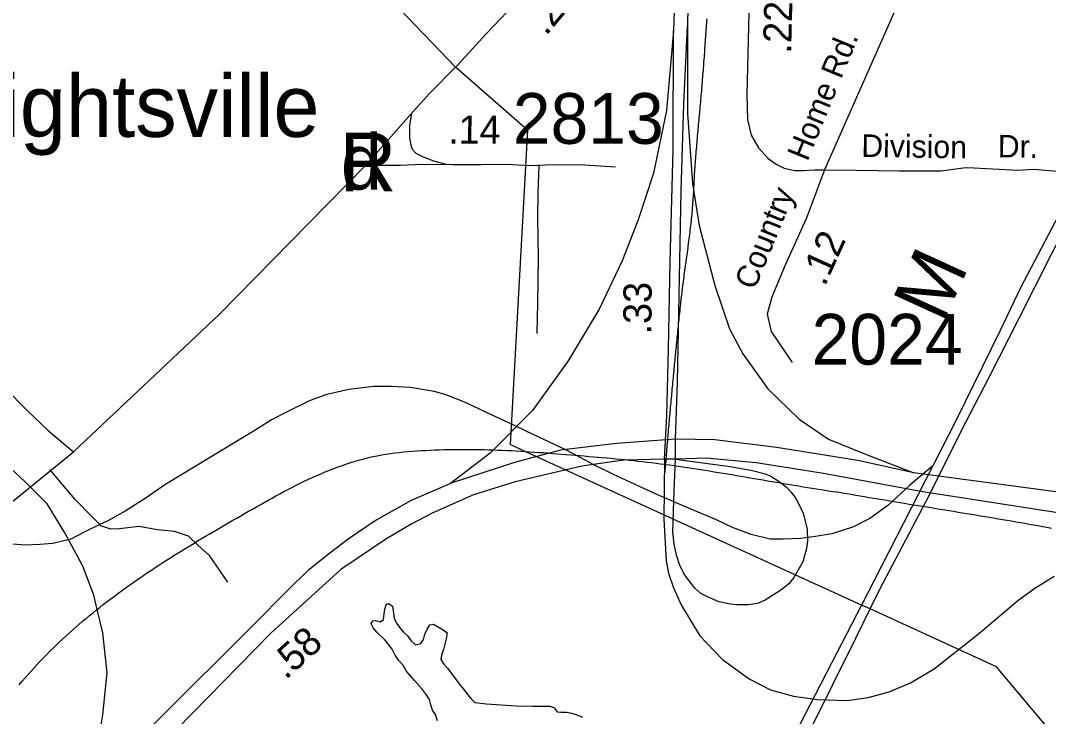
# Model space of a CAD drawing. Extents: x 1945482 to 2853149, y 66427 to 1015778.
# Drawn here: x 2321253 to 2324243, y 186898 to 188923 of the extents above; entities that cross this region are included whole.
import ezdxf

# ---------------------------------------------------------------- set-up
doc = ezdxf.new("R2010")
doc.units = 0
for name, color, linetype in [('Old_Level_11', 7, 'Continuous'), ('Old_Level_17', 7, 'Continuous'), ('Old_Level_22', 7, 'Continuous'), ('Old_Level_28', 7, 'Continuous'), ('Old_Level_29', 7, 'Continuous'), ('Old_Level_3', 7, 'Continuous'), ('Old_Level_32', 7, 'Continuous'), ('Old_Level_35', 7, 'Continuous'), ('Old_Level_44', 7, 'Continuous'), ('Old_Level_47', 7, 'Continuous'), ('Old_Level_56', 7, 'Continuous'), ('Old_Level_60', 7, 'Continuous'), ('Old_Level_8', 7, 'Continuous'), ('Old_Level_9', 7, 'Continuous')]:
    doc.layers.add(name, color=color, linetype=linetype)

msp = doc.modelspace()

# ---------------------------------------------------------------- linework, layer by layer
at = {"layer": 'Old_Level_28'}
for points in [[(2324358.8, 187539.7), (2323851.7, 187607.2), (2323688.9, 187643.3), (2323451.6, 187680.9), (2323272.1, 187703.2), (2323157.8, 187705.3), (2322986.2, 187693), (2322823.1, 187673), (2322689.2, 187637.3), (2322508.7, 187577.8), (2322388.6, 187526.7), (2322287.2, 187469.7), (2322206.2, 187414.6), (2322152.2, 187373.5), (2322090.6, 187323.8), (2322050.6, 187285.9), (2321910.1, 187144.3), (2321439.2, 186676.5), (2321001.4, 186215.9)], [(2323157.6, 187647), (2323126.2, 187647), (2323007.9, 187643.8), (2322885.3, 187626.5), (2322691.9, 187581.1), (2322570.8, 187543.2), (2322449.8, 187490.3), (2322389.3, 187457.8), (2322315.8, 187414.6), (2322184, 187325.9), (2321980.4, 187141.1), (2321479.8, 186629.1), (2321013.9, 186156.8), (2320894, 186050.2), (2320819.9, 185996.3), (2320726.4, 185933.9)], [(2326441.1, 186811.7), (2326329.8, 186851.1), (2325970.9, 186988), (2325480.1, 187171.9), (2325231.8, 187262.1), (2325037.1, 187326.4), (2324893, 187367.4), (2324842, 187381.6), (2324765.1, 187400.8), (2324566.3, 187441.8), (2324251.6, 187493.8), (2323877.8, 187552), (2323588.7, 187605.7), (2323393.2, 187636.6), (2323248.3, 187650.3), (2323157.6, 187647)]]:
    msp.add_lwpolyline(points, dxfattribs=at)
at = {"layer": 'Old_Level_29'}
for points in [[(2323173.2, 189388.6), (2323167.7, 189289.3), (2323160.7, 189154.9), (2323159.3, 189100.9), (2323152.7, 188893.5)], [(2323209.2, 189384.9), (2323204.4, 189263), (2323197.4, 189130), (2323194.7, 189026), (2323192.7, 188905.4)], [(2323126.2, 187647), (2323132.7, 187773.5), (2323138.1, 187967), (2323143, 188221.1), (2323151.1, 188547.5), (2323152.7, 188893.5)], [(2323157.6, 187647), (2323157.8, 187705.3), (2323164, 187870.8), (2323174.8, 188427.5), (2323182.4, 188680.5), (2323192.7, 188905.4)]]:
    msp.add_lwpolyline(points, dxfattribs=at)
at = {"layer": 'Old_Level_3'}
for points in [[(2323248.9, 188928.1), (2323248.5, 188921.6), (2323248, 188915), (2323247.5, 188908.5), (2323247.1, 188901.9), (2323246.6, 188895.4), (2323246.1, 188888.8), (2323245.7, 188882.3), (2323245.2, 188875.7), (2323244.8, 188869.2), (2323244.3, 188862.6), (2323243.8, 188856.1), (2323243.4, 188849.5), (2323242.9, 188843), (2323242.4, 188836.5), (2323242, 188829.9), (2323241.5, 188823.4), (2323241, 188816.8), (2323240.5, 188810.3), (2323240, 188803.7), (2323239.6, 188797.2), (2323239.1, 188790.6), (2323238.6, 188784.1), (2323238.1, 188777.6), (2323237.6, 188771), (2323237, 188764.5), (2323236.5, 188757.9), (2323236, 188751.4), (2323235.5, 188744.9), (2323234.9, 188738.3)], [(2323234.9, 188738.3), (2323234.4, 188731.8), (2323233.8, 188725.2), (2323233.3, 188718.7), (2323232.7, 188712.2), (2323232.1, 188705.6), (2323231.6, 188699.1), (2323231, 188692.6), (2323230.4, 188686), (2323229.8, 188679.5), (2323229.2, 188672.9), (2323228.6, 188666.4), (2323228.1, 188659.9), (2323227.5, 188653.3), (2323226.9, 188646.8), (2323226.3, 188640.3), (2323225.7, 188633.7), (2323225.1, 188627.2), (2323224.5, 188620.7), (2323223.9, 188614.1), (2323223.3, 188607.6), (2323222.7, 188601.1), (2323222.1, 188594.5), (2323221.5, 188588), (2323220.9, 188581.5), (2323220.4, 188574.9), (2323219.8, 188568.4), (2323219.2, 188561.8), (2323218.7, 188555.3), (2323218.1, 188548.8), (2323217.6, 188542.2), (2323217, 188535.7), (2323216.5, 188529.2), (2323216, 188522.6), (2323215.4, 188516.1), (2323214.9, 188509.5), (2323214.5, 188503), (2323214, 188496.4), (2323213.6, 188489.9), (2323213.2, 188483.3), (2323212.8, 188476.8), (2323212.4, 188470.2), (2323212.1, 188463.7), (2323211.7, 188457.1), (2323211.4, 188450.6), (2323211, 188444), (2323210.7, 188437.5), (2323210.3, 188430.9), (2323210, 188424.3), (2323209.6, 188417.8), (2323209.2, 188411.2), (2323208.8, 188404.7), (2323208.4, 188398.1), (2323207.9, 188391.6), (2323207.5, 188385.1), (2323207, 188378.5), (2323206.4, 188372), (2323205.9, 188365.4), (2323205.2, 188358.9), (2323204.6, 188352.4), (2323203.9, 188345.9), (2323203.2, 188339.3), (2323202.5, 188332.8), (2323201.7, 188326.3), (2323201, 188319.8), (2323200.2, 188313.3), (2323199.4, 188306.8), (2323198.6, 188300.3), (2323197.7, 188293.8), (2323196.9, 188287.2), (2323196.1, 188280.7), (2323195.2, 188274.2), (2323194.3, 188267.7), (2323193.5, 188261.2), (2323192.6, 188254.7), (2323191.7, 188248.2), (2323190.8, 188241.7), (2323189.9, 188235.2), (2323189, 188228.7), (2323188.1, 188222.2), (2323187.2, 188215.7), (2323186.3, 188209.2), (2323185.4, 188202.7), (2323184.5, 188196.2), (2323183.7, 188189.7), (2323182.8, 188183.2), (2323181.9, 188176.7), (2323181, 188170.2), (2323180.2, 188163.7), (2323179.3, 188157.2), (2323178.5, 188150.7), (2323177.7, 188144.1), (2323176.9, 188137.6), (2323176.1, 188131.1), (2323175.3, 188124.6), (2323174.6, 188118.1), (2323173.8, 188111.6), (2323173.1, 188105), (2323172.4, 188098.5), (2323171.7, 188092)], [(2323171.7, 188092), (2323171, 188085.5), (2323170.3, 188079), (2323169.6, 188072.4), (2323168.9, 188065.9), (2323168.2, 188059.4), (2323167.5, 188052.9), (2323166.8, 188046.3), (2323166.2, 188039.8), (2323165.5, 188033.3), (2323164.8, 188026.7), (2323164.2, 188020.2), (2323163.5, 188013.7), (2323162.8, 188007.2), (2323162.2, 188000.6), (2323161.6, 187994.1), (2323160.9, 187987.6), (2323160.3, 187981), (2323159.6, 187974.5), (2323159, 187968), (2323158.4, 187961.4), (2323157.7, 187954.9), (2323157.1, 187948.4), (2323156.5, 187941.9), (2323155.9, 187935.3), (2323155.2, 187928.8), (2323154.6, 187922.3), (2323154, 187915.7), (2323153.4, 187909.2), (2323152.8, 187902.7), (2323152.2, 187896.1), (2323151.6, 187889.6), (2323150.9, 187883.1), (2323150.3, 187876.5), (2323149.7, 187870), (2323149.1, 187863.5), (2323148.5, 187856.9), (2323147.9, 187850.4), (2323147.3, 187843.9), (2323146.7, 187837.3), (2323146.1, 187830.8), (2323145.5, 187824.2), (2323144.9, 187817.7), (2323144.3, 187811.2), (2323143.7, 187804.6), (2323143, 187798.1), (2323142.4, 187791.6), (2323141.8, 187785), (2323141.2, 187778.5), (2323140.6, 187772), (2323140, 187765.4), (2323139.5, 187758.9), (2323138.9, 187752.4), (2323138.3, 187745.8), (2323137.7, 187739.3), (2323137.2, 187732.8), (2323136.6, 187726.2), (2323136.1, 187719.7), (2323135.5, 187713.1), (2323135, 187706.6), (2323134.4, 187700.1), (2323133.9, 187693.5), (2323133.3, 187687), (2323132.8, 187680.5), (2323132.2, 187673.9), (2323131.7, 187667.4), (2323131.1, 187660.8), (2323130.6, 187654.3), (2323130.1, 187647.8), (2323129.5, 187641.2), (2323129, 187634.7), (2323128.7, 187631.8), (2323128.4, 187628.1), (2323127.9, 187621.6), (2323127.3, 187615.1), (2323126.7, 187608.3)], [(2321155.8, 186347.6), (2321330.2, 186509), (2321427.1, 186664), (2321472.3, 186786.7), (2321491.6, 186903), (2321504.6, 187025.7), (2321491.6, 187142), (2321475.6, 187210), (2321465.8, 187251.7), (2321433.5, 187335.7), (2321381.9, 187432.6), (2321330.2, 187516.5), (2321265.6, 187581.1), (2321181.6, 187658.6)], [(2321578.9, 187287), (2321589.7, 187294.5), (2321600.5, 187302), (2321611.4, 187309.4), (2321622.4, 187316.8), (2321633.4, 187324.2), (2321644.4, 187331.5), (2321655.4, 187338.7), (2321666.5, 187345.9), (2321677.7, 187353.1), (2321688.8, 187360.2), (2321700, 187367.3), (2321711.2, 187374.3), (2321722.5, 187381.3), (2321733.7, 187388.2), (2321745, 187395.1), (2321756.3, 187402), (2321767.6, 187408.9), (2321779, 187415.7), (2321790.4, 187422.5), (2321801.7, 187429.2), (2321813.1, 187435.9), (2321824.5, 187442.6), (2321835.9, 187449.3), (2321847.4, 187455.9), (2321858.8, 187462.5), (2321870.2, 187469.1), (2321881.6, 187475.6), (2321893.1, 187482.2), (2321904.5, 187488.7), (2321915.9, 187495.2), (2321927.4, 187501.6), (2321938.8, 187508.1), (2321950.2, 187514.5), (2321961.6, 187520.9), (2321973, 187527.3), (2321984.4, 187533.7), (2321995.8, 187540.1), (2322007.3, 187546.4), (2322018.9, 187552.6), (2322030.6, 187558.8), (2322042.3, 187564.9), (2322054.2, 187570.9), (2322066.1, 187576.9), (2322078.1, 187582.7), (2322090.2, 187588.4), (2322102.3, 187594), (2322114.5, 187599.4), (2322126.8, 187604.7), (2322139.1, 187609.9), (2322151.4, 187614.9), (2322163.9, 187619.8), (2322176.3, 187624.4), (2322188.8, 187628.9), (2322201.4, 187633.2), (2322214, 187637.3), (2322226.6, 187641.2), (2322239.3, 187644.8), (2322252, 187648.3), (2322264.7, 187651.4), (2322277.5, 187654.4), (2322290.2, 187657.1), (2322303, 187659.5), (2322315.8, 187661.6), (2322328.6, 187663.5), (2322341.4, 187665.1), (2322354.3, 187666.5), (2322367.1, 187667.8), (2322380, 187669), (2322392.9, 187670), (2322405.9, 187671), (2322418.8, 187671.9), (2322431.8, 187672.6), (2322444.8, 187673.3), (2322457.8, 187673.9), (2322470.9, 187674.4), (2322483.9, 187674.8), (2322497, 187675.1), (2322510.1, 187675.3), (2322523.2, 187675.4), (2322536.3, 187675.5), (2322549.5, 187675.5), (2322562.6, 187675.4), (2322575.8, 187675.2), (2322588.9, 187675), (2322602.1, 187674.7), (2322615.3, 187674.3), (2322628.5, 187673.9), (2322641.7, 187673.4), (2322654.9, 187672.9), (2322668.1, 187672.3), (2322681.3, 187671.7), (2322694.6, 187671), (2322707.8, 187670.2), (2322721, 187669.4), (2322734.2, 187668.6), (2322747.5, 187667.7), (2322760.7, 187666.8), (2322773.9, 187665.9), (2322787.1, 187664.9)], [(2322787.1, 187664.9), (2322800.3, 187663.9), (2322813.5, 187662.9), (2322826.7, 187661.8), (2322839.9, 187660.8), (2322853.1, 187659.7), (2322866.3, 187658.6), (2322879.4, 187657.4), (2322892.6, 187656.3), (2322905.7, 187655.1), (2322918.9, 187654), (2322932, 187652.8), (2322945.1, 187651.7), (2322958.2, 187650.5), (2322971.2, 187649.4), (2322984.3, 187648.2), (2322997.3, 187647), (2323010.4, 187645.8), (2323023.4, 187644.4), (2323036.4, 187643.1), (2323049.5, 187641.6), (2323062.5, 187640.1), (2323075.5, 187638.6), (2323088.5, 187637), (2323101.5, 187635.4), (2323114.5, 187633.7), (2323127.5, 187632), (2323128.7, 187631.8), (2323140.5, 187630.2), (2323153.5, 187628.4), (2323166.5, 187626.5), (2323179.5, 187624.6), (2323192.4, 187622.7), (2323205.4, 187620.7), (2323218.4, 187618.7), (2323231.4, 187616.7), (2323244.3, 187614.7), (2323257.3, 187612.6), (2323270.3, 187610.5), (2323283.2, 187608.4), (2323296.2, 187606.3), (2323309.1, 187604.1), (2323322.1, 187601.9), (2323335.1, 187599.7), (2323348, 187597.6), (2323361, 187595.4), (2323373.9, 187593.1), (2323386.9, 187590.9), (2323399.8, 187588.7), (2323412.8, 187586.5), (2323425.7, 187584.3), (2323438.7, 187582), (2323451.6, 187579.8), (2323464.6, 187577.6), (2323477.6, 187575.4), (2323490.5, 187573.2), (2323503.5, 187571.1), (2323516.4, 187568.9), (2323529.4, 187566.7), (2323542.4, 187564.6), (2323555.3, 187562.5), (2323568.3, 187560.4), (2323581.3, 187558.4), (2323594.2, 187556.3), (2323607.2, 187554.3), (2323624.6, 187551.7)], [(2324251.8, 187445.6), (2324238.9, 187447.9), (2324226, 187450.2), (2324213.1, 187452.5), (2324200.1, 187454.8), (2324187.2, 187457.1), (2324174.3, 187459.4), (2324161.4, 187461.6), (2324148.4, 187463.9), (2324135.5, 187466.1), (2324122.6, 187468.3), (2324109.6, 187470.5), (2324096.7, 187472.7), (2324083.7, 187474.9), (2324070.8, 187477.1), (2324057.9, 187479.3), (2324044.9, 187481.4), (2324032, 187483.6), (2324019, 187485.7), (2324006.1, 187487.9), (2323993.1, 187490), (2323980.2, 187492.2), (2323967.2, 187494.3), (2323954.3, 187496.4), (2323941.3, 187498.5), (2323928.4, 187500.7), (2323915.4, 187502.8), (2323902.5, 187504.9), (2323889.5, 187507), (2323876.6, 187509.2), (2323863.6, 187511.3), (2323850.7, 187513.4), (2323837.7, 187515.5), (2323824.8, 187517.7), (2323811.8, 187519.8), (2323798.9, 187521.9), (2323785.9, 187524.1), (2323773, 187526.2), (2323760, 187528.4), (2323747.1, 187530.5), (2323734.2, 187532.7), (2323721.2, 187534.9), (2323708.3, 187537), (2323695.3, 187539.3), (2323682.4, 187541.5), (2323669.5, 187543.8), (2323656.6, 187546.1), (2323643.6, 187548.3), (2323624.6, 187551.7)], [(2321248.8, 186990.8), (2321257.4, 187000.7), (2321266, 187010.6), (2321274.7, 187020.5), (2321283.4, 187030.2), (2321292.2, 187039.9), (2321301.1, 187049.5), (2321310, 187059.1), (2321319, 187068.5), (2321328.1, 187077.9), (2321337.2, 187087.2), (2321346.5, 187096.4), (2321355.8, 187105.5), (2321365.2, 187114.5), (2321374.7, 187123.4), (2321384.2, 187132.2), (2321393.9, 187141), (2321403.6, 187149.7), (2321413.4, 187158.3), (2321423.2, 187166.8), (2321433.2, 187175.2), (2321443.2, 187183.6), (2321453.2, 187192), (2321463.4, 187200.2), (2321473.6, 187208.4), (2321475.6, 187210), (2321483.9, 187216.5), (2321494.2, 187224.6), (2321504.6, 187232.6), (2321515, 187240.5), (2321525.5, 187248.4), (2321536.1, 187256.2), (2321546.7, 187264), (2321557.4, 187271.7), (2321568.1, 187279.4), (2321578.9, 187287)]]:
    msp.add_lwpolyline(points, dxfattribs=at)
at = {"layer": 'Old_Level_32'}
for points in [[(2322256.7, 188502.7), (2322396, 188659.1), (2322443.1, 188711.3), (2322518.1, 188787.6), (2322525.6, 188795.2), (2322606.9, 188884.7), (2322688.6, 188970.1), (2322753.3, 189047.3), (2322802.2, 189106.1), (2322838.2, 189142.9), (2322892.6, 189211.2), (2322939.9, 189277.4), (2322964.9, 189306.4), (2322996.5, 189332.6), (2323046.9, 189364.6), (2323113.1, 189383.6), (2323148.7, 189388.6), (2323192.4, 189388.9)], [(2323192.4, 189388.9), (2323270.5, 189372.8), (2323312, 189354), (2323331, 189339.1), (2323357.2, 189311.5), (2323369.9, 189281), (2323376.4, 189253.4), (2323378.6, 189210.5), (2323375.7, 189106.6), (2323365.5, 188706.9), (2323367.3, 188634.9), (2323378.2, 188589.9), (2323399.3, 188552.8), (2323427.6, 188521.6), (2323451.2, 188504.8), (2323474.1, 188493.2), (2323505, 188486.7), (2323530.4, 188486.7), (2323562.7, 188488.9), (2323588.5, 188488.9)], [(2320640.1, 186908.8), (2320712, 187026.3), (2320730.3, 187059.1), (2320751.2, 187092), (2320786.4, 187139.4), (2320829.4, 187188.1), (2320871.9, 187228), (2320915.5, 187264.3), (2320981, 187320.8), (2321024.3, 187354.7), (2321075.8, 187398.3), (2321109.3, 187426.9), (2321119, 187435), (2321407, 187668.2), (2321830.2, 188067.4), (2322091.5, 188333.9), (2322256.7, 188502.7)], [(2322256.7, 188502.7), (2322358.2, 188502.1), (2322420.3, 188505.2), (2322510.3, 188504.7), (2322592.2, 188504.2), (2322666.2, 188505.5), (2322735.2, 188500.9), (2322802.3, 188503.9), (2322894.3, 188503.4), (2322983.9, 188497.5)], [(2323591.4, 188488.9), (2323683.3, 188488.1), (2323809.7, 188486), (2323931, 188486), (2323994.7, 188495), (2324008.7, 188495.5), (2324154.5, 188487.5), (2324201, 188491.1), (2324279.3, 188484.3), (2324315.5, 188482.1), (2324333.4, 188476.8), (2324381.7, 188485.7), (2324419.3, 188514.4)], [(2323591.4, 188488.9), (2323568.2, 188426.4), (2323538.4, 188346.4), (2323476.3, 188209.1), (2323438.8, 188117.8), (2323424.5, 188068.7), (2323436.6, 188018.5), (2323497.3, 187928.3)]]:
    msp.add_lwpolyline(points, dxfattribs=at)
at = {"layer": 'Old_Level_35'}
for points in [[(2323917.8, 189227), (2323591.4, 188488.9)], [(2322755.7, 188012.2), (2322757.9, 188101.9), (2322759.7, 188232), (2322757.5, 188347.9), (2322758.4, 188422), (2322761.5, 188502.1)], [(2321034.8, 188009.5), (2321120.1, 187926.9), (2321207, 187854.3), (2321271.6, 187788.8), (2321334, 187729.3), (2321407, 187668.2)], [(2321483, 187456.6), (2321460.1, 187480.4), (2321411.1, 187529.7), (2321338, 187617)], [(2321856, 187289.4), (2321802.2, 187366.3), (2321769.6, 187395.8), (2321741.1, 187423.3), (2321700.9, 187436.7), (2321650.7, 187441.7), (2321596.5, 187450.8), (2321540.8, 187443.8), (2321514.8, 187443.4), (2321486.6, 187452.8), (2321483, 187456.6)]]:
    msp.add_lwpolyline(points, dxfattribs=at)
at = {"layer": 'Old_Level_44'}
for points in [[(2323196.4, 186174.6), (2323245.6, 186270.8), (2323263.9, 186306.7), (2323274.4, 186327.2), (2323324.2, 186424.6), (2323341.3, 186457.9), (2323363.5, 186501.3), (2323549.4, 186858.8), (2323682.8, 187126.2), (2323724.1, 187211.1), (2323751.3, 187267), (2323818.3, 187393.6), (2323896.5, 187540.8), (2323989.1, 187728.5), (2324069, 187881.7), (2324158.1, 188057.3), (2324252.7, 188245.1), (2324330.9, 188392.3), (2324354.7, 188440)], [(2324327.4, 188458.5), (2324311.4, 188429.5), (2324162.6, 188147.5), (2324101.6, 188019.1), (2323975.8, 187762), (2323907.1, 187627.2)], [(2323907.1, 187627.2), (2323839.3, 187570.5), (2323775.6, 187512), (2323723.1, 187473.9), (2323676, 187450), (2323612.8, 187429.5), (2323565.1, 187421.6), (2323521.3, 187415.9), (2323471.4, 187413.9), (2323433.3, 187414.4), (2323378.7, 187428.2), (2323323.9, 187448.1), (2323277, 187470.2), (2323193.6, 187504.9), (2323110.1, 187541.6), (2323053.1, 187567.4), (2322977.7, 187602.4), (2322920.6, 187630.1), (2322840.8, 187673), (2322723.8, 187728.8), (2322689.9, 187745), (2322610.4, 187781.9), (2322547.2, 187811.4), (2322488.3, 187835.1), (2322455.9, 187843.8), (2322387.4, 187855.1), (2322331.3, 187858.8), (2322279.2, 187858.8), (2322207.6, 187849.9), (2322144.1, 187835.4), (2322094.8, 187817.5), (2322028.1, 187784.8), (2321983, 187761), (2321932.2, 187729), (2321672.3, 187572.6), (2321617.8, 187534.5), (2321557.3, 187496.1), (2321506.4, 187468), (2321483, 187456.6), (2321439.7, 187435.4), (2321398.5, 187413.7), (2321347, 187401.7), (2321309.1, 187398.2), (2321267.2, 187396.5), (2321217, 187400.5)], [(2323907.1, 187627.2), (2323736.2, 187294.4), (2323699.1, 187222.5), (2323611.7, 187053.4), (2323548.5, 186930.8), (2323492.8, 186822.6), (2323427.9, 186694), (2323342.5, 186526.5), (2323315.7, 186475.9), (2323296.4, 186439.4), (2323262.4, 186375.3), (2323242.9, 186336.8), (2323233.4, 186318.1), (2323215.1, 186282.2), (2323165.9, 186185.4)]]:
    msp.add_lwpolyline(points, dxfattribs=at)
at = {"layer": 'Old_Level_47'}
for points in [[(2323152.7, 188893.5), (2323131.8, 188661.7), (2323093.6, 188479.1), (2323049.1, 188342.9), (2323003.1, 188224.1), (2322936.4, 188083.6), (2322846, 187933.5), (2322742.4, 187788.1), (2322618.5, 187664.2), (2322503.7, 187576.2)], [(2323192.7, 188905.4), (2323193.2, 188653.5), (2323207.3, 188449.2), (2323226.7, 188327), (2323272.6, 188151.9), (2323315.3, 188026.5), (2323354.2, 187953), (2323426.6, 187851.3), (2323517.8, 187763.5), (2323603.6, 187705.3), (2323711.3, 187661.1), (2323851.7, 187607.2)], [(2322390.5, 188653), (2322384.1, 188618.8), (2322384.1, 188581.9), (2322388, 188560.8), (2322392, 188548.9), (2322402.5, 188537), (2322422.3, 188527.8), (2322454, 188514.6), (2322491.1, 188504.8)], [(2323126.2, 187647), (2323124.1, 187471.9), (2323130.5, 187350.8), (2323137.5, 187315.6), (2323152.2, 187273), (2323175.5, 187221.1), (2323229, 187132.5), (2323295, 187063.9), (2323372.7, 187007.9), (2323434.5, 186976.2), (2323500.9, 186957.8), (2323571.1, 186947.7), (2323657.2, 186944.4), (2323718.2, 186953.6), (2323780, 186970.3), (2323841.8, 186996.2), (2323910.8, 187037.2), (2324044.5, 187142.5), (2324154.3, 187236.2), (2324203.2, 187272.1), (2324260, 187306.4)], [(2323150, 187436), (2323154.3, 187556.2), (2323157.6, 187647)], [(2323157.6, 187647), (2323317.5, 187625.4), (2323382.3, 187613.5), (2323415.7, 187604.8), (2323435.8, 187597.3), (2323459.2, 187582.2), (2323480.9, 187565.5), (2323494.3, 187551.3), (2323508.5, 187532.1), (2323529.4, 187491.1), (2323541.1, 187442.6), (2323541.9, 187409.2), (2323539.4, 187387.5), (2323528.5, 187348.2), (2323502.6, 187302.2), (2323487.6, 187283.8), (2323465, 187265.4), (2323419.1, 187237), (2323396.5, 187227), (2323369.8, 187222.8), (2323336.3, 187222.8), (2323318, 187225.3), (2323284.5, 187232), (2323251.1, 187246.2), (2323231.9, 187256.2), (2323214.4, 187272.1), (2323185.4, 187309.8), (2323170.9, 187337.3), (2323160.8, 187368.1), (2323154.2, 187399.2), (2323150, 187436)]]:
    msp.add_lwpolyline(points, dxfattribs=at)
at = {"layer": 'Old_Level_56'}
for p, q in [((2322727.1, 188604.1), (2322518.1, 188787.6)), ((2322724.8, 187667.7), (2322677.5, 187689.3)), ((2323699.1, 187222.5), (2322724.8, 187667.7)), ((2323724.1, 187211.1), (2323699.1, 187222.5))]:
    msp.add_line(p, q, dxfattribs=at)
for points in [[(2322518.1, 188787.6), (2320726, 190655.5), (2321161.7, 192135.8), (2321162.4, 192138.3)], [(2322727.1, 188604.1), (2322677.5, 187689.3)], [(2324503.8, 186552.4), (2324092.3, 187042.8), (2323724.1, 187211.1)]]:
    msp.add_lwpolyline(points, dxfattribs=at)
at = {"layer": 'Old_Level_60'}
for points in [[(2322432.7, 186962.5), (2322421.5, 186977.8), (2322398.7, 187002.6), (2322374.7, 187031.3), (2322364.7, 187048.5), (2322352.2, 187062.5), (2322342.7, 187076.6), (2322333.7, 187093.7), (2322324.5, 187106.4), (2322313, 187120.1), (2322288.7, 187144), (2322278.2, 187156.7), (2322272.2, 187168.9), (2322277.5, 187176.2), (2322285, 187177.6), (2322298.5, 187173.6), (2322309, 187180.4), (2322310.2, 187197.3), (2322312.5, 187210.7), (2322317.5, 187225.9), (2322325.5, 187226), (2322334.5, 187219.6), (2322339.5, 187184.1), (2322346.2, 187170), (2322356.2, 187156.4), (2322367, 187143.7), (2322379, 187131.5), (2322389.2, 187118.6), (2322402, 187106.3), (2322416.7, 187110.4), (2322425.2, 187122), (2322429, 187138.1), (2322435.5, 187152.1), (2322443.5, 187165.2), (2322453.7, 187166.7), (2322482.5, 187150.7), (2322493.5, 187141.5), (2322491.2, 187124.4), (2322482.7, 187092.9), (2322477.2, 187076.5), (2322475.7, 187064), (2322484.2, 187050.8), (2322494.5, 187039.3), (2322532, 186989.5), (2322542.7, 186976.8), (2322552.5, 186961.9), (2322563.5, 186949.8), (2322574.7, 186939.1), (2322608.2, 186935.5), (2322695, 186929.5), (2322742.2, 186928), (2322793, 186928.7), (2322805.5, 186923.7), (2322813.5, 186912.3), (2322825.5, 186910.5), (2322841, 186911.2), (2322856.2, 186907.9), (2322871.5, 186903), (2322887.5, 186896.5)], [(2322465.7, 186886), (2322459.7, 186903.7), (2322451.2, 186916.4), (2322446, 186932.2), (2322442, 186948), (2322432.7, 186962.5)]]:
    msp.add_lwpolyline(points, dxfattribs=at)

# ---------------------------------------------------------------- texts
at = {"layer": 'Old_Level_11'}
for s, height, rotation, p in [('Country    Home Rd.', 65.617, 67.7302, (2323388.5, 188136.5)), ('Division', 65.62, 359.1485, (2323698.4, 188526.5)), ('Dr.', 65.62, 359.1243, (2324095.4, 188525.1))]:
    msp.add_text(s, height=height, rotation=rotation, dxfattribs=at).set_placement(p)
at = {"layer": 'Old_Level_17'}
for s, rotation, p in [('.25', 50.0034, (2322781.4, 188876.7)), ('.22', 88.5426, (2323494.4, 188826.4)), ('.14', 359.7406, (2322496.6, 188565)), ('.12', 65.6868, (2323592.4, 188147.2)), ('.33', 89.7316, (2323088, 188009.7)), ('.58', 42.2283, (2322023.9, 187003.4))]:
    msp.add_text(s, height=82.02, rotation=rotation, dxfattribs=at).set_placement(p)
at = {"layer": 'Old_Level_22'}
msp.add_text('M', height=164, rotation=65.447, dxfattribs=at).set_placement((2323935.9, 188039.8))
at = {"layer": 'Old_Level_8'}
for s, p in [('2813', (2322684.7, 188564.4)), ('2024', (2323554.1, 187922))]:
    msp.add_text(s, height=147.64, dxfattribs=at).set_placement(p)
at = {"layer": 'Old_Level_9'}
for s, height, p in [('Hightsville', 180.446, (2321022.8, 188584.5)), ('d', 160.8, (2322184.6, 188431.2)), ('R', 170.6, (2322181.1, 188426.2))]:
    msp.add_text(s, height=height, dxfattribs=at).set_placement(p)

doc.saveas('drawing.dxf')
